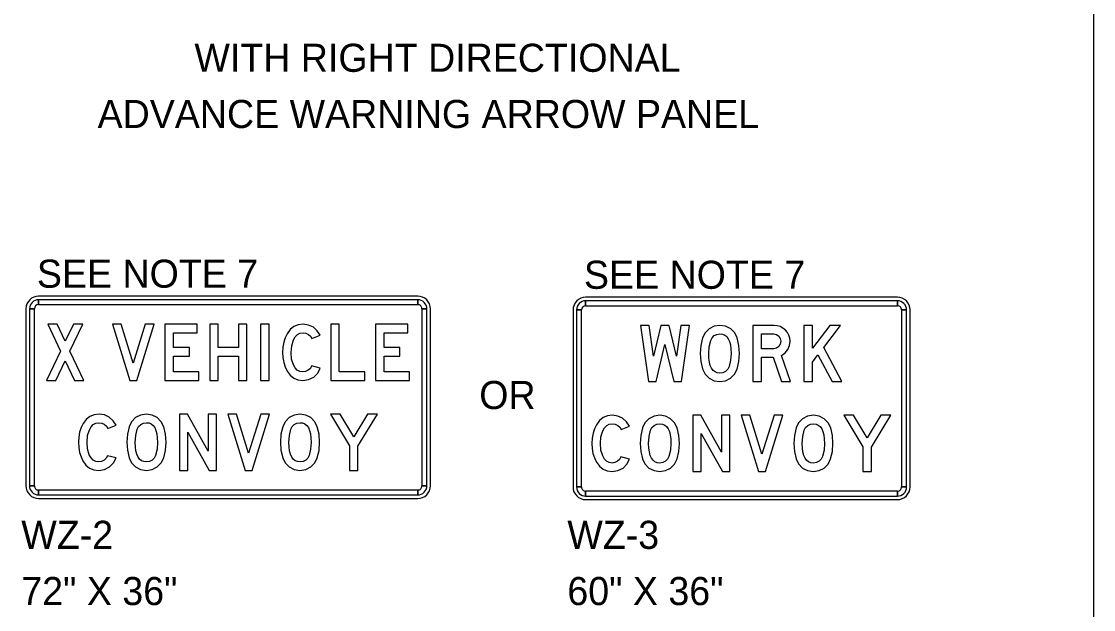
# Model space of a CAD drawing. Extents: x 1373848 to 1374003, y 380642 to 381248.
# Drawn here: x 1373931.58 to 1373954.48, y 381043.07 to 381055.63 of the extents above; entities that cross this region are included whole.
import ezdxf

# ---------------------------------------------------------------- set-up
doc = ezdxf.new("R2010")
doc.units = 0
doc.layers.add('Working Level 1', color=7, linetype='Continuous')

msp = doc.modelspace()

# ---------------------------------------------------------------- linework, layer by layer
at = {"layer": 'Working Level 1'}
for p, q in [((1373954.481, 381081.277), (1373954.481, 380977.045)), ((1373940.044, 381049.76), (1373931.945, 381049.76)), ((1373950.291, 381049.737), (1373943.631, 381049.737)), ((1373931.675, 381049.491), (1373931.675, 381045.711)), ((1373931.75, 381049.491), (1373931.855, 381049.491)), ((1373931.945, 381049.581), (1373931.945, 381049.685)), ((1373940.044, 381049.685), (1373940.044, 381049.581)), ((1373940.134, 381049.491), (1373940.239, 381049.491)), ((1373940.314, 381045.711), (1373940.314, 381049.491)), ((1373943.631, 381049.557), (1373943.631, 381049.662)), ((1373950.291, 381049.662), (1373950.291, 381049.557)), ((1373943.361, 381049.467), (1373943.361, 381045.687)), ((1373943.436, 381049.467), (1373943.541, 381049.467)), ((1373950.381, 381049.467), (1373950.486, 381049.467)), ((1373950.561, 381045.687), (1373950.561, 381049.467)), ((1373931.855, 381045.711), (1373931.75, 381045.711)), ((1373931.945, 381045.516), (1373931.945, 381045.621)), ((1373940.044, 381045.621), (1373940.044, 381045.516)), ((1373940.239, 381045.711), (1373940.134, 381045.711)), ((1373943.541, 381045.687), (1373943.436, 381045.687)), ((1373943.631, 381045.492), (1373943.631, 381045.597)), ((1373950.291, 381045.597), (1373950.291, 381045.492)), ((1373950.486, 381045.687), (1373950.381, 381045.687)), ((1373931.945, 381045.441), (1373940.044, 381045.441)), ((1373943.631, 381045.417), (1373950.291, 381045.417))]:
    msp.add_line(p, q, dxfattribs=at)
for points in [[(1373931.75, 381049.491), (1373931.75, 381045.711), (1373931.855, 381045.711), (1373931.855, 381049.491), (1373931.75, 381049.491)], [(1373940.044, 381049.685), (1373931.945, 381049.685), (1373931.945, 381049.581), (1373940.044, 381049.581), (1373940.044, 381049.685)], [(1373940.239, 381045.711), (1373940.239, 381049.491), (1373940.134, 381049.491), (1373940.134, 381045.711), (1373940.239, 381045.711)], [(1373950.291, 381049.662), (1373943.631, 381049.662), (1373943.631, 381049.557), (1373950.291, 381049.557), (1373950.291, 381049.662)], [(1373943.436, 381049.467), (1373943.436, 381045.687), (1373943.541, 381045.687), (1373943.541, 381049.467), (1373943.436, 381049.467)], [(1373950.486, 381045.687), (1373950.486, 381049.467), (1373950.381, 381049.467), (1373950.381, 381045.687), (1373950.486, 381045.687)], [(1373932.914, 381047.961), (1373932.615, 381048.589), (1373932.889, 381049.16), (1373932.689, 381049.16), (1373932.515, 381048.798), (1373932.342, 381049.16), (1373932.141, 381049.16), (1373932.414, 381048.588), (1373932.113, 381047.961), (1373932.314, 381047.961), (1373932.514, 381048.378), (1373932.714, 381047.961)], [(1373934.413, 381049.16), (1373934.224, 381049.16), (1373933.966, 381048.331), (1373933.709, 381049.16), (1373933.52, 381049.16), (1373933.891, 381047.961), (1373934.04, 381047.961)], [(1373935.37, 381048.142), (1373934.826, 381048.142), (1373934.826, 381048.481), (1373935.165, 381048.481), (1373935.165, 381048.662), (1373934.826, 381048.662), (1373934.826, 381048.979), (1373935.333, 381048.979), (1373935.333, 381049.16), (1373934.644, 381049.16), (1373934.644, 381047.961), (1373935.37, 381047.961)], [(1373936.393, 381047.961), (1373936.393, 381049.16), (1373936.212, 381049.16), (1373936.212, 381048.662), (1373935.782, 381048.662), (1373935.782, 381049.16), (1373935.601, 381049.16), (1373935.601, 381047.961), (1373935.782, 381047.961), (1373935.782, 381048.481), (1373936.212, 381048.481), (1373936.212, 381047.961)], [(1373936.869, 381047.961), (1373936.869, 381049.16), (1373936.688, 381049.16), (1373936.688, 381047.961)], [(1373937.958, 381048.227), (1373937.776, 381048.273), (1373937.75, 381048.22), (1373937.706, 381048.178), (1373937.649, 381048.151), (1373937.587, 381048.142), (1373937.524, 381048.151), (1373937.47, 381048.18), (1373937.424, 381048.228), (1373937.387, 381048.294), (1373937.35, 381048.418), (1373937.338, 381048.56), (1373937.351, 381048.704), (1373937.389, 381048.828), (1373937.427, 381048.894), (1373937.473, 381048.941), (1373937.528, 381048.97), (1373937.593, 381048.979), (1373937.653, 381048.971), (1373937.707, 381048.946), (1373937.753, 381048.907), (1373937.784, 381048.857), (1373937.958, 381048.925), (1373937.899, 381049.021), (1373937.814, 381049.096), (1373937.71, 381049.144), (1373937.596, 381049.16), (1373937.49, 381049.148), (1373937.398, 381049.11), (1373937.319, 381049.048), (1373937.254, 381048.96), (1373937.211, 381048.874), (1373937.181, 381048.778), (1373937.163, 381048.674), (1373937.157, 381048.561), (1373937.163, 381048.448), (1373937.181, 381048.344), (1373937.21, 381048.249), (1373937.253, 381048.163), (1373937.317, 381048.074), (1373937.394, 381048.011), (1373937.485, 381047.973), (1373937.59, 381047.961), (1373937.712, 381047.979), (1373937.821, 381048.034), (1373937.907, 381048.12)], [(1373938.914, 381047.961), (1373938.914, 381048.142), (1373938.369, 381048.142), (1373938.369, 381049.16), (1373938.188, 381049.16), (1373938.188, 381047.961)], [(1373939.87, 381048.142), (1373939.326, 381048.142), (1373939.326, 381048.481), (1373939.665, 381048.481), (1373939.665, 381048.662), (1373939.326, 381048.662), (1373939.326, 381048.979), (1373939.833, 381048.979), (1373939.833, 381049.16), (1373939.145, 381049.16), (1373939.145, 381047.961), (1373939.87, 381047.961)], [(1373945.848, 381049.137), (1373945.665, 381049.137), (1373945.572, 381048.48), (1373945.414, 381049.137), (1373945.239, 381049.137), (1373945.08, 381048.479), (1373944.988, 381049.137), (1373944.805, 381049.137), (1373944.973, 381047.937), (1373945.136, 381047.937), (1373945.326, 381048.726), (1373945.516, 381047.937), (1373945.68, 381047.937)], [(1373946.918, 381048.538), (1373946.905, 381048.709), (1373946.869, 381048.869), (1373946.815, 381048.977), (1373946.729, 381049.063), (1373946.62, 381049.118), (1373946.498, 381049.137), (1373946.376, 381049.118), (1373946.268, 381049.063), (1373946.183, 381048.977), (1373946.129, 381048.868), (1373946.092, 381048.708), (1373946.08, 381048.538), (1373946.092, 381048.368), (1373946.129, 381048.207), (1373946.183, 381048.098), (1373946.268, 381048.012), (1373946.376, 381047.956), (1373946.498, 381047.937), (1373946.62, 381047.955), (1373946.728, 381048.011), (1373946.814, 381048.096), (1373946.868, 381048.205), (1373946.905, 381048.366)], [(1373948.006, 381047.937), (1373947.816, 381048.497), (1373947.89, 381048.549), (1373947.948, 381048.622), (1373947.985, 381048.707), (1373947.997, 381048.8), (1373947.991, 381048.867), (1373947.972, 381048.929), (1373947.941, 381048.986), (1373947.898, 381049.038), (1373947.845, 381049.081), (1373947.788, 381049.112), (1373947.725, 381049.131), (1373947.658, 381049.137), (1373947.205, 381049.137), (1373947.205, 381047.937), (1373947.386, 381047.937), (1373947.386, 381048.458), (1373947.637, 381048.458), (1373947.815, 381047.937)], [(1373949.105, 381047.937), (1373948.716, 381048.668), (1373949.076, 381049.137), (1373948.848, 381049.137), (1373948.474, 381048.651), (1373948.474, 381049.137), (1373948.293, 381049.137), (1373948.293, 381047.937), (1373948.474, 381047.937), (1373948.474, 381048.354), (1373948.594, 381048.51), (1373948.9, 381047.937)], [(1373946.737, 381048.537), (1373946.726, 381048.391), (1373946.694, 381048.256), (1373946.665, 381048.199), (1373946.62, 381048.155), (1373946.564, 381048.127), (1373946.5, 381048.118), (1373946.443, 381048.125), (1373946.395, 381048.144), (1373946.354, 381048.177), (1373946.321, 381048.223), (1373946.294, 381048.282), (1373946.276, 381048.354), (1373946.265, 381048.439), (1373946.261, 381048.537), (1373946.272, 381048.682), (1373946.304, 381048.817), (1373946.332, 381048.874), (1373946.377, 381048.918), (1373946.434, 381048.946), (1373946.5, 381048.956), (1373946.555, 381048.949), (1373946.603, 381048.93), (1373946.644, 381048.897), (1373946.677, 381048.851), (1373946.703, 381048.792), (1373946.722, 381048.72), (1373946.733, 381048.635)], [(1373947.386, 381048.639), (1373947.386, 381048.956), (1373947.65, 381048.956), (1373947.708, 381048.944), (1373947.757, 381048.909), (1373947.789, 381048.858), (1373947.801, 381048.797), (1373947.789, 381048.736), (1373947.757, 381048.685), (1373947.708, 381048.65), (1373947.65, 381048.639)], [(1373933.599, 381046.307), (1373933.417, 381046.353), (1373933.39, 381046.3), (1373933.346, 381046.258), (1373933.29, 381046.231), (1373933.227, 381046.222), (1373933.164, 381046.231), (1373933.11, 381046.26), (1373933.065, 381046.308), (1373933.028, 381046.374), (1373932.991, 381046.498), (1373932.979, 381046.64), (1373932.991, 381046.784), (1373933.029, 381046.908), (1373933.067, 381046.974), (1373933.114, 381047.021), (1373933.169, 381047.05), (1373933.233, 381047.059), (1373933.293, 381047.051), (1373933.348, 381047.026), (1373933.393, 381046.987), (1373933.424, 381046.937), (1373933.599, 381047.005), (1373933.54, 381047.101), (1373933.454, 381047.176), (1373933.35, 381047.224), (1373933.236, 381047.24), (1373933.131, 381047.228), (1373933.039, 381047.19), (1373932.96, 381047.128), (1373932.894, 381047.04), (1373932.852, 381046.954), (1373932.822, 381046.858), (1373932.804, 381046.754), (1373932.798, 381046.641), (1373932.803, 381046.528), (1373932.821, 381046.424), (1373932.851, 381046.329), (1373932.893, 381046.243), (1373932.957, 381046.154), (1373933.035, 381046.091), (1373933.126, 381046.053), (1373933.23, 381046.041), (1373933.352, 381046.059), (1373933.462, 381046.114), (1373933.548, 381046.2)], [(1373934.667, 381046.641), (1373934.654, 381046.812), (1373934.618, 381046.973), (1373934.564, 381047.081), (1373934.478, 381047.167), (1373934.369, 381047.222), (1373934.247, 381047.24), (1373934.125, 381047.222), (1373934.017, 381047.167), (1373933.931, 381047.081), (1373933.878, 381046.972), (1373933.841, 381046.811), (1373933.829, 381046.641), (1373933.841, 381046.471), (1373933.878, 381046.31), (1373933.931, 381046.201), (1373934.017, 381046.115), (1373934.125, 381046.059), (1373934.247, 381046.041), (1373934.369, 381046.059), (1373934.477, 381046.114), (1373934.563, 381046.2), (1373934.617, 381046.308), (1373934.654, 381046.469)], [(1373935.746, 381046.041), (1373935.746, 381047.24), (1373935.565, 381047.24), (1373935.565, 381046.452), (1373935.128, 381047.24), (1373934.954, 381047.24), (1373934.954, 381046.041), (1373935.135, 381046.041), (1373935.135, 381046.855), (1373935.586, 381046.041)], [(1373936.879, 381047.24), (1373936.689, 381047.24), (1373936.432, 381046.411), (1373936.174, 381047.24), (1373935.985, 381047.24), (1373936.357, 381046.041), (1373936.506, 381046.041)], [(1373937.948, 381046.641), (1373937.935, 381046.812), (1373937.899, 381046.973), (1373937.845, 381047.081), (1373937.759, 381047.167), (1373937.65, 381047.222), (1373937.528, 381047.24), (1373937.406, 381047.222), (1373937.298, 381047.167), (1373937.213, 381047.081), (1373937.159, 381046.972), (1373937.122, 381046.811), (1373937.11, 381046.641), (1373937.122, 381046.471), (1373937.159, 381046.31), (1373937.213, 381046.201), (1373937.298, 381046.115), (1373937.406, 381046.059), (1373937.528, 381046.041), (1373937.65, 381046.059), (1373937.758, 381046.114), (1373937.844, 381046.2), (1373937.898, 381046.308), (1373937.935, 381046.469)], [(1373939.185, 381047.24), (1373938.972, 381047.24), (1373938.678, 381046.761), (1373938.39, 381047.24), (1373938.179, 381047.24), (1373938.586, 381046.566), (1373938.586, 381046.041), (1373938.767, 381046.041), (1373938.767, 381046.561)], [(1373944.565, 381046.284), (1373944.384, 381046.33), (1373944.357, 381046.277), (1373944.313, 381046.235), (1373944.257, 381046.208), (1373944.194, 381046.198), (1373944.131, 381046.208), (1373944.077, 381046.237), (1373944.032, 381046.284), (1373943.995, 381046.351), (1373943.958, 381046.474), (1373943.946, 381046.617), (1373943.958, 381046.761), (1373943.996, 381046.884), (1373944.034, 381046.95), (1373944.081, 381046.998), (1373944.136, 381047.026), (1373944.2, 381047.036), (1373944.26, 381047.027), (1373944.315, 381047.003), (1373944.36, 381046.963), (1373944.391, 381046.913), (1373944.565, 381046.982), (1373944.507, 381047.078), (1373944.421, 381047.153), (1373944.317, 381047.201), (1373944.203, 381047.217), (1373944.097, 381047.204), (1373944.005, 381047.167), (1373943.926, 381047.104), (1373943.861, 381047.017), (1373943.819, 381046.93), (1373943.789, 381046.835), (1373943.77, 381046.731), (1373943.764, 381046.618), (1373943.77, 381046.505), (1373943.788, 381046.401), (1373943.818, 381046.306), (1373943.86, 381046.22), (1373943.924, 381046.131), (1373944.002, 381046.068), (1373944.093, 381046.03), (1373944.197, 381046.017), (1373944.319, 381046.036), (1373944.429, 381046.091), (1373944.514, 381046.176)], [(1373945.633, 381046.618), (1373945.621, 381046.789), (1373945.585, 381046.949), (1373945.53, 381047.058), (1373945.444, 381047.143), (1373945.336, 381047.198), (1373945.214, 381047.217), (1373945.092, 381047.198), (1373944.984, 381047.143), (1373944.898, 381047.057), (1373944.845, 381046.948), (1373944.808, 381046.788), (1373944.796, 381046.618), (1373944.808, 381046.448), (1373944.845, 381046.287), (1373944.898, 381046.178), (1373944.984, 381046.092), (1373945.092, 381046.036), (1373945.214, 381046.017), (1373945.336, 381046.036), (1373945.444, 381046.091), (1373945.529, 381046.176), (1373945.584, 381046.285), (1373945.621, 381046.446)], [(1373946.713, 381046.017), (1373946.713, 381047.217), (1373946.532, 381047.217), (1373946.532, 381046.428), (1373946.095, 381047.217), (1373945.921, 381047.217), (1373945.921, 381046.017), (1373946.102, 381046.017), (1373946.102, 381046.831), (1373946.553, 381046.017)], [(1373947.845, 381047.217), (1373947.656, 381047.217), (1373947.398, 381046.388), (1373947.141, 381047.217), (1373946.952, 381047.217), (1373947.324, 381046.017), (1373947.473, 381046.017)], [(1373948.914, 381046.618), (1373948.902, 381046.789), (1373948.866, 381046.949), (1373948.812, 381047.058), (1373948.726, 381047.143), (1373948.617, 381047.198), (1373948.495, 381047.217), (1373948.373, 381047.198), (1373948.265, 381047.143), (1373948.179, 381047.057), (1373948.126, 381046.948), (1373948.089, 381046.788), (1373948.077, 381046.618), (1373948.089, 381046.448), (1373948.126, 381046.287), (1373948.179, 381046.178), (1373948.265, 381046.092), (1373948.373, 381046.036), (1373948.495, 381046.017), (1373948.617, 381046.036), (1373948.725, 381046.091), (1373948.81, 381046.176), (1373948.865, 381046.285), (1373948.902, 381046.446)], [(1373950.151, 381047.217), (1373949.939, 381047.217), (1373949.644, 381046.738), (1373949.356, 381047.217), (1373949.146, 381047.217), (1373949.553, 381046.543), (1373949.553, 381046.017), (1373949.734, 381046.017), (1373949.734, 381046.538)], [(1373934.485, 381046.64), (1373934.475, 381046.495), (1373934.443, 381046.359), (1373934.414, 381046.303), (1373934.369, 381046.259), (1373934.312, 381046.231), (1373934.248, 381046.222), (1373934.192, 381046.228), (1373934.144, 381046.248), (1373934.103, 381046.28), (1373934.069, 381046.326), (1373934.043, 381046.385), (1373934.025, 381046.457), (1373934.013, 381046.542), (1373934.01, 381046.64), (1373934.021, 381046.786), (1373934.052, 381046.921), (1373934.081, 381046.977), (1373934.126, 381047.022), (1373934.183, 381047.05), (1373934.248, 381047.059), (1373934.304, 381047.053), (1373934.352, 381047.033), (1373934.392, 381047), (1373934.426, 381046.955), (1373934.452, 381046.896), (1373934.471, 381046.824), (1373934.481, 381046.738)], [(1373937.767, 381046.64), (1373937.756, 381046.495), (1373937.724, 381046.359), (1373937.695, 381046.303), (1373937.65, 381046.259), (1373937.594, 381046.231), (1373937.53, 381046.222), (1373937.473, 381046.228), (1373937.425, 381046.248), (1373937.384, 381046.28), (1373937.351, 381046.326), (1373937.324, 381046.385), (1373937.306, 381046.457), (1373937.295, 381046.542), (1373937.291, 381046.64), (1373937.302, 381046.786), (1373937.334, 381046.921), (1373937.362, 381046.977), (1373937.407, 381047.022), (1373937.464, 381047.05), (1373937.53, 381047.059), (1373937.585, 381047.053), (1373937.633, 381047.033), (1373937.674, 381047), (1373937.707, 381046.955), (1373937.733, 381046.896), (1373937.752, 381046.824), (1373937.763, 381046.738)], [(1373945.452, 381046.617), (1373945.442, 381046.471), (1373945.41, 381046.336), (1373945.381, 381046.279), (1373945.336, 381046.235), (1373945.279, 381046.208), (1373945.215, 381046.198), (1373945.159, 381046.205), (1373945.111, 381046.224), (1373945.07, 381046.257), (1373945.036, 381046.303), (1373945.01, 381046.362), (1373944.992, 381046.434), (1373944.98, 381046.519), (1373944.977, 381046.617), (1373944.987, 381046.762), (1373945.019, 381046.897), (1373945.048, 381046.954), (1373945.093, 381046.998), (1373945.15, 381047.026), (1373945.215, 381047.036), (1373945.27, 381047.029), (1373945.319, 381047.01), (1373945.359, 381046.977), (1373945.393, 381046.931), (1373945.419, 381046.872), (1373945.437, 381046.8), (1373945.448, 381046.715)], [(1373948.733, 381046.617), (1373948.723, 381046.471), (1373948.691, 381046.336), (1373948.662, 381046.279), (1373948.617, 381046.235), (1373948.56, 381046.208), (1373948.496, 381046.198), (1373948.44, 381046.205), (1373948.392, 381046.224), (1373948.351, 381046.257), (1373948.317, 381046.303), (1373948.291, 381046.362), (1373948.273, 381046.434), (1373948.261, 381046.519), (1373948.258, 381046.617), (1373948.269, 381046.762), (1373948.3, 381046.897), (1373948.329, 381046.954), (1373948.374, 381046.998), (1373948.431, 381047.026), (1373948.496, 381047.036), (1373948.552, 381047.029), (1373948.6, 381047.01), (1373948.64, 381046.977), (1373948.674, 381046.931), (1373948.7, 381046.872), (1373948.718, 381046.8), (1373948.729, 381046.715)], [(1373931.945, 381045.516), (1373940.044, 381045.516), (1373940.044, 381045.621), (1373931.945, 381045.621), (1373931.945, 381045.516)], [(1373943.631, 381045.492), (1373950.291, 381045.492), (1373950.291, 381045.597), (1373943.631, 381045.597), (1373943.631, 381045.492)]]:
    msp.add_lwpolyline(points, close=True, dxfattribs=at)
for centre, radius, start, end in [((1373931.945, 381049.491), 0.27, 90.0002, 179.9998), ((1373940.044, 381049.491), 0.27, 0, 90.0002), ((1373943.631, 381049.467), 0.27, 90.0002, 179.9998), ((1373950.291, 381049.467), 0.27, 0, 90.0002), ((1373931.945, 381049.491), 0.195, 90.0002, 179.9998), ((1373931.945, 381049.491), 0.09, 90.0002, 179.9998), ((1373940.044, 381049.491), 0.195, 0, 90.0002), ((1373940.044, 381049.491), 0.09, 0, 90.0002), ((1373943.631, 381049.467), 0.195, 90.0002, 179.9998), ((1373943.631, 381049.467), 0.09, 90.0002, 179.9998), ((1373950.291, 381049.467), 0.195, 0, 90.0002), ((1373950.291, 381049.467), 0.09, 0, 90.0002), ((1373931.945, 381045.711), 0.27, 179.9998, 270.0001), ((1373931.945, 381045.711), 0.195, 179.9998, 270.0001), ((1373931.945, 381045.711), 0.09, 179.9998, 270.0001), ((1373940.044, 381045.711), 0.27, 270.0001, 0.0003), ((1373940.044, 381045.711), 0.195, 270.0001, 0.0003), ((1373940.044, 381045.711), 0.09, 270.0001, 0.0003), ((1373943.631, 381045.687), 0.27, 179.9998, 270.0001), ((1373943.631, 381045.687), 0.195, 179.9998, 270.0001), ((1373943.631, 381045.687), 0.09, 179.9998, 270.0001), ((1373950.291, 381045.687), 0.27, 270.0001, 0.0003), ((1373950.291, 381045.687), 0.195, 270.0001, 0.0003), ((1373950.291, 381045.687), 0.09, 270.0001, 0.0003)]:
    msp.add_arc(centre, radius, start, end, dxfattribs=at)

# ---------------------------------------------------------------- texts
for s, p in [('WITH RIGHT DIRECTIONAL', (1373935.274, 381054.551)), ('ADVANCE WARNING ARROW PANEL', (1373933.205, 381053.351)), ('SEE NOTE 7 ', (1373931.908, 381049.941)), ('SEE NOTE 7 ', (1373943.595, 381049.918))]:
    msp.add_text(s, height=0.6, dxfattribs=at).set_placement(p)
for s, p in [('OR', (1373941.358, 381047.351)), ('WZ-2', (1373931.575, 381044.365)), ('WZ-3', (1373943.24, 381044.365)), ('72" X 36"', (1373931.575, 381043.165)), ('60" X 36"', (1373943.24, 381043.165))]:
    msp.add_text(s, height=0.6, rotation=0, dxfattribs=at).set_placement(p)

doc.saveas('drawing.dxf')
